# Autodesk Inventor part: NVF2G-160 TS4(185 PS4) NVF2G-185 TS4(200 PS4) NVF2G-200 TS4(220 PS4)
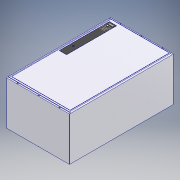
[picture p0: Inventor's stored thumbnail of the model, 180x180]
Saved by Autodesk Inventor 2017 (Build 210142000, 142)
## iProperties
Part Number: NVF2G-160 TS4(185 PS4) NVF2G-185 TS4(200 PS4) NVF2G-200 TS4(220 PS4)
Material: Типовые
Document SubType Name: Modeling
Designer: RSagdiev
Density: 1 g/cm^3
Appearance: По умолчанию
Author: RSagdiev
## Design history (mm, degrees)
sketch "Эскиз1"
  geometry: L1 (0, 0)-(44.679, 0) reference; L2 (0, 0)-(0, 56.035) reference; L3 (0, 0)-(892, 0); L4 (892, 0)-(892, 374.6); L5 (892, 374.6)-(0, 374.6); L6 (0, 374.6)-(0, 0)
  constraints: 12 end point, 3 horizontal, 2 parallel, 2 vertical, 1 perpendicular
  dimensions: "d0" = 892 distance of L5.end L4.end; "d1" = 374.6 distance of L4.end L3.end
extrude "Выдавливание1" new body sketch "Эскиз1" stored distance "d2" = 540; taper "d3" = 0 deg
sketch "Эскиз2"
  geometry: L1 (0, 0)-(0, 892) reference; L2 (540, 0)-(540, 892) reference; L3 (0, 892)-(150, 892); L4 (540, 892)-(540, 880); L5 (540, 0)-(390, 0); L6 (0, 0)-(0, 12); L7 (0, 892)-(540, 892) reference; L8 (0, 892)-(150, 892); L9 (150, 892)-(150, 880); L10 (150, 880)-(0, 880); L11 (0, 880)-(0, 892); L12 (540, 892)-(390, 892); L13 (390, 892)-(390, 880); L14 (390, 880)-(540, 880); L15 (540, 880)-(540, 892); L16 (0, 0)-(540, 0) reference; L17 (0, 0)-(150, 0); L18 (150, 0)-(150, 12); L19 (150, 12)-(0, 12); L20 (0, 12)-(0, 0); L21 (540, 0)-(390, 0); L22 (390, 0)-(390, 12); L23 (390, 12)-(540, 12); L24 (540, 12)-(540, 0); L25 (150, 892)-(390, 892); L26 (0, 880)-(0, 892); L27 (390, 892)-(540, 892); L28 (540, 880)-(540, 12); L29 (390, 0)-(150, 0); L30 (540, 12)-(540, 0); L31 (150, 0)-(0, 0); L32 (0, 12)-(0, 880); L33 (150, 880)-(390, 880); L34 (150, 12)-(390, 12); 1 further point
  constraints: 60 end point, 26 parallel, 13 perpendicular, 7 horizontal
  dimensions: "d4" = 150 distance of L9.end L10.end; "d5" = 12 distance of L3.end L9.end; "d6" = 150 distance of L4.end L13.end; "d7" = 12 distance of L13.end L12.end; "d8" = 150 distance of L6.end L18.end; "d9" = 12 distance of L18.end L17.end; "d10" = 150 distance of L22.end L23.end; "d11" = 12 distance of L5.end L22.end
extrude "Выдавливание2" new body sketch "Эскиз2" distance "d12" = 4; taper "d13" = 0 deg
sketch "Эскиз3"
  geometry: L1 (520, 25)-(520, 876); L2 (20, 876)-(520, 876); L3 (20, 876)-(20, 25); L4 (20, 876)-(520, 876); L5 (20, 25)-(520, 25); L6 (0, 880)-(0, 12) reference; L7 (540, 12)-(540, 880) reference; L8 (0, 892)-(540, 892) reference; L9 (0, 0)-(540, 0) reference; 1 further point
  constraints: 11 end point, 2 perpendicular, 1 horizontal
  dimensions: "d162" = 20 distance between parallel lines of L6 L3 (derived); "d164" = 20 distance between parallel lines of L7 L1; "d203" = 16 distance between parallel lines of L2 L8; "d204" = 25 distance between parallel lines of L9 L5
extrude "Выдавливание3" new body sketch "Эскиз3" distance "d17" = 2; taper "d18" = 0 deg
sketch "Эскиз4"
  geometry: L1 (91, 852)-(32, 852); L2 (30, 850)-(30, 424); L3 (32, 422)-(91, 422); L4 (93, 424)-(93, 850); L5 (0, 892)-(540, 892) reference; L6 (0, 880)-(0, 12) reference; A1 r 2 centre (32, 850) between (32, 852) and (30, 850); A2 r 2 centre (91, 850) between (93, 850) and (91, 852); A3 r 2 centre (91, 424) between (91, 422) and (93, 424); A4 r 2 centre (32, 424) between (30, 424) and (32, 422); 6 further points
  constraints: 8 end point, 8 point on circle, 8 tangent, 6 point on line, 4 centre point, 3 equal radius, 2 parallel, 1 horizontal, 1 perpendicular
  dimensions: "d20" = 63 distance of point (93, 422) point (30, 422); "d21" = 430 distance of point (30, 422) point (30, 852); "d24" = 2 radius of A1; "d165" = 40 distance between parallel lines of L5 L1; "d166" = 30 distance between parallel lines of L6 L2
extrude "Выдавливание4" cut sketch "Эскиз4" distance "d25" = 0.6; taper "d26" = 0 deg
sketch "Эскиз5"
  geometry: L1 (0, 892)-(540, 892) reference; L2 (0, 0)-(0, 892) reference; L3 (540, 892)-(540, 0) reference; L4 (0, 0)-(540, 0) reference; C1 r 5 at (90, 886); C2 r 5 at (270, 886); C3 r 5 at (90, 6); C4 r 5 at (270, 6); C5 r 5 at (450, 886); C6 r 5 at (450, 6); 1 further point
  constraints: 6 centre point
  dimensions: "d27" = 10 diameter of C1; "d28" = 6 distance from line of C1.centre L1; "d30" = 10 diameter of C2; "d31" = 6 distance from line of C2.centre L1; "d33" = 10 diameter of C3; "d34" = 6 distance from line of L4 C3.centre; "d36" = 10 diameter of C4; "d38" = 6 distance from line of C4.centre L4; "d169" = 180 distance of C1.centre C2.centre; "d172" = 180 distance of C4.centre C3.centre (derived); "d205" = 10 diameter of C5; "d206" = 180 distance of C5.centre C2.centre (derived); "d207" = 10 diameter of C6; "d208" = 180 distance of C6.centre C4.centre (derived); "d209" = 540 distance between parallel lines of L3 L2 (derived); "d210" = 90 distance from line of L2 C1.centre (derived); "d211" = 90 distance from line of L2 C3.centre (derived)
extrude "Выдавливание5" cut sketch "Эскиз5" stored distance "d39" = 0.6; taper "d40" = 0 deg
sketch "Эскиз6"
  geometry: L1 (30, 761)-(30, 817); L2 (91, 759)-(32, 759); L3 (93, 850)-(93, 817); L4 (32, 852)-(91, 852); L5 (30, 761)-(30, 850); L6 (30, 817)-(93, 817); L7 (93, 850)-(93, 817); L8 (30, 817)-(30, 850); L9 (93, 817)-(93, 761); L10 (43.5, 828)-(79.5, 828); L11 (81.5, 830)-(81.5, 840); L12 (79.5, 842)-(43.5, 842); L13 (41.5, 840)-(41.5, 830); L14 (41.5, 828)-(81.5, 842); L15 (81.5, 828)-(41.5, 842); L16 (61.5, 805.5)-(61.5, 770.857); L17 (53.25, 805.5)-(53.25, 770.857); L18 (69.75, 770.857)-(69.75, 805.5); L19 (47, 812)-(36, 812); L20 (35, 811)-(35, 800); L21 (36, 799)-(47, 799); L22 (48, 800)-(48, 811); L23 (48, 812)-(35, 799); L24 (35, 812)-(48, 799); L25 (81.5, 830)-(81.5, 765.5); L26 (41.5, 805.5)-(88.409, 805.5); L27 (39.654, 788.179)-(85.729, 788.179); L28 (39.654, 770.857)-(84.963, 770.857); L29 (88, 800)-(88, 811); L30 (76, 799)-(87, 799); L31 (88, 812)-(75, 799); L32 (75, 812)-(88, 799); L33 (75, 811)-(75, 800); L34 (87, 812)-(76, 812); L35 (88, 782.679)-(88, 793.679); L36 (76, 781.679)-(87, 781.679); L37 (88, 794.679)-(75, 781.679); L38 (75, 794.679)-(88, 781.679); L39 (75, 793.679)-(75, 782.679); L40 (87, 794.679)-(76, 794.679); L41 (88, 765.357)-(88, 776.357); L42 (76, 764.357)-(87, 764.357); L43 (88, 777.357)-(75, 764.357); L44 (75, 777.357)-(88, 764.357); L45 (75, 776.357)-(75, 765.357); L46 (87, 777.357)-(76, 777.357); L47 (48, 765.357)-(48, 776.357); L48 (36, 764.357)-(47, 764.357); L49 (48, 777.357)-(35, 764.357); L50 (35, 777.357)-(48, 764.357); L51 (35, 776.357)-(35, 765.357); L52 (47, 777.357)-(36, 777.357); L53 (48, 782.679)-(48, 793.679); L54 (36, 781.679)-(47, 781.679); L55 (48, 794.679)-(35, 781.679); L56 (35, 794.679)-(48, 781.679); L57 (35, 793.679)-(35, 782.679); L58 (47, 794.679)-(36, 794.679); L59 (91, 759)-(32, 759); L60 (0, 892)-(540, 892) reference; L61 (0, 878)-(0, 14); L62 (93, 817)-(93, 761); C1 r 6.5 at (61.5, 805.5); C2 r 6.5 at (61.5, 770.857); C3 r 6.5 at (61.5, 788.179); A1 r 2 centre (43.5, 840) between (43.5, 842) and (41.5, 840); A2 r 2 centre (79.5, 840) between (81.5, 840) and (79.5, 842); A3 r 2 centre (79.5, 830) between (79.5, 828) and (81.5, 830); A4 r 2 centre (43.5, 830) between (41.5, 830) and (43.5, 828); A5 r 8.25 centre (61.5, 805.5) between (69.75, 805.5) and (53.25, 805.5); A6 r 8.25 centre (61.5, 770.857) between (53.25, 770.857) and (69.75, 770.857); A7 r 1 centre (47, 811) between (48, 811) and (47, 812); A8 r 1 centre (47, 800) between (47, 799) and (48, 800); A9 r 1 centre (36, 800) between (35, 800) and (36, 799); A10 r 1 centre (36, 811) between (36, 812) and (35, 811); A11 r 1 centre (87, 800) between (87, 799) and (88, 800); A12 r 1 centre (87, 811) between (88, 811) and (87, 812); A13 r 1 centre (76, 811) between (76, 812) and (75, 811); A14 r 1 centre (76, 800) between (75, 800) and (76, 799); A15 r 1 centre (87, 782.679) between (87, 781.679) and (88, 782.679); A16 r 1 centre (87, 793.679) between (88, 793.679) and (87, 794.679); A17 r 1 centre (76, 793.679) between (76, 794.679) and (75, 793.679); A18 r 1 centre (76, 782.679) between (75, 782.679) and (76, 781.679); A19 r 1 centre (87, 765.357) between (87, 764.357) and (88, 765.357); A20 r 1 centre (87, 776.357) between (88, 776.357) and (87, 777.357); A21 r 1 centre (76, 776.357) between (76, 777.357) and (75, 776.357); A22 r 1 centre (76, 765.357) between (75, 765.357) and (76, 764.357); A23 r 1 centre (47, 765.357) between (47, 764.357) and (48, 765.357); A24 r 1 centre (47, 776.357) between (48, 776.357) and (47, 777.357); A25 r 1 centre (36, 776.357) between (36, 777.357) and (35, 776.357); A26 r 1 centre (36, 765.357) between (35, 765.357) and (36, 764.357); A27 r 1 centre (47, 782.679) between (47, 781.679) and (48, 782.679); A28 r 1 centre (47, 793.679) between (48, 793.679) and (47, 794.679); A29 r 1 centre (36, 793.679) between (36, 794.679) and (35, 793.679); A30 r 1 centre (36, 782.679) between (35, 782.679) and (36, 781.679); A31 r 2 centre (32, 850) between (32, 852) and (30, 850); A32 r 2 centre (91, 850) between (93, 850) and (91, 852); A33 r 2 centre (91, 761) between (91, 759) and (93, 761); A34 r 2 centre (32, 761) between (30, 761) and (32, 759); 15 further points
  constraints: 124 end point, 70 tangent, 68 point on circle, 67 point on line, 37 centre point, 21 equal radius, 15 midpoint, 15 parallel, 11 horizontal, 7 collinear, 7 perpendicular, 3 coincident, 2 vertical
  dimensions: "d43" = 35 distance between parallel lines of L4 L6; "d44" = 40 distance of L15.end L14.end; "d45" = 14 distance of L14.end L15.start; "d46" = 10 distance between parallel lines of L4 L12; "d47" = 2 radius of A1; "d48" = 11.5 distance between parallel lines of L8 L13; "d49" = 16.5 diameter of A6; "d50" = 31.5 distance between parallel lines of L1 L16; "d51" = 11.5 distance from line of L6 L16.start; "d52" = 11.85714 distance from line of L2 L16.end; "d53" = 13 diameter of C1; "d54" = 13 diameter of C2; "d55" = 13 diameter of C3; "d56" = 13 distance of L24.end L23.end; "d57" = 13 distance of L23.end L24.start; "d58" = 1 radius of A7 (derived); "d59" = 11.5 distance from line of L6 L26.start; "d60" = 11.5 distance from line of L5 L26.start; "d61" = 13 distance of L32.end L31.end; "d62" = 13 distance of L31.end L32.start; "d63" = 1 radius of A12 (derived); "d64" = 13 distance of L38.end L37.end; "d65" = 13 distance of L37.end L38.start; "d66" = 1 radius of A16 (derived); "d67" = 13 distance of L44.end L43.end; "d68" = 13 distance of L43.end L44.start; "d69" = 1 radius of A20 (derived); "d70" = 13 distance of L50.end L49.end; "d71" = 13 distance of L49.end L50.start; "d72" = 1 radius of A24 (derived); "d73" = 13 distance of L56.end L55.end; "d74" = 13 distance of L55.end L56.start; "d75" = 1 radius of A28 (derived); "d146" = 40 distance of point (81.5, 805.5) L26.start; "d147" = 4.32143 distance between parallel lines of L40 L30; "d148" = 4.32143 distance between parallel lines of L46 L36; "d149" = 93 distance between parallel lines of L2 L4; "d151" = 2 radius of A31; "d152" = 2 radius of A32; "d153" = 2 radius of A33; "d154" = 2 radius of A34; "d167" = 40 distance between parallel lines of L4 L60 (derived); "d168" = 30 distance between parallel lines of L61 L5 (derived)
extrude "Выдавливание6" new body sketch "Эскиз6" distance "d76" = 0.3; taper "d77" = 0 deg
extrude "Выдавливание7" new body sketch "Эскиз6" distance "d78" = 0.6; taper "d79" = 0 deg
sketch "Эскиз7"
  geometry: L1 (30, 817)-(93, 817) reference; L2 (30, 817)-(93, 817); L3 (93, 817)-(93, 817.1); L4 (93, 817.1)-(30, 817.1); L5 (30, 817.1)-(30, 817); 4 further points; 1 other entity
  constraints: 8 end point, 2 parallel, 1 horizontal, 1 perpendicular, 2 other
  dimensions: "d80" = 0.1 distance of L3.end L2.end
extrude "Выдавливание8" cut sketch "Эскиз7" distance "d81" = 0.3; taper "d82" = 0 deg
sketch "Эскиз8" dims "d91" = 10
  geometry: L1 (30, 817.1)-(93, 817.1) reference; C1 r 1 at (38, 822.1); C2 r 1 at (45.75, 822.1); C3 r 1 at (53.5, 822.1); C4 r 1 at (61.25, 822.1); C5 r 1 at (69, 822.1); C6 r 1 at (76.75, 822.1); C7 r 1 at (84.5, 822.1); 4 further points; 1 other entity
  constraints: 7 centre point, 1 horizontal, 13 other
  dimensions: "d83" = 2 diameter of C1; "d84" = 5 distance from line of C1.centre L1; "d85" = 8 dimension on C1.centre; "d88" = 7.75 distance of C1.centre C2.centre
extrude "Выдавливание9" join sketch "Эскиз8" distance "d93" = 0.3; taper "d94" = 0 deg
sketch "Эскиз9"
  geometry: C1 r 6.5 at (0, 0) reference; C2 r 7.5 at (0, 0); 1 further point
  constraints: 1 centre point, 1 coincident
  dimensions: "d95" = 15 diameter of C2
extrude "Выдавливание10" join sketch "Эскиз9" distance "d96" = 9.4; taper "d97" = -3 deg
sketch "Эскиз10"
  geometry: L1 (0, 7.331)-(0.619, 6.259); L2 (0.619, 6.259)-(-0.619, 6.259); L3 (-0.619, 6.259)-(0, 7.331); 2 further points
  constraints: 6 end point, 7 other
sketch "Эскиз11"
  geometry: L1 (0, 7.917)-(0.884, 6.386); L2 (0.884, 6.386)-(-0.884, 6.386); L3 (-0.884, 6.386)-(0, 7.917); 2 further points
  constraints: 6 end point, 7 other
feature "Лофт1" sketch "Эскиз10", "Эскиз11" dims "d98" = 0, "d99" = 90 deg, "d100" = 0, "d101" = 90 deg
sketch "Эскиз12"
  geometry: L1 (38.299, 807.492)-(44.519, 807.492); L2 (44.519, 807.492)-(44.519, 803.992); L3 (44.519, 803.992)-(38.299, 803.992); L4 (38.299, 803.992)-(38.299, 807.492); L5 (37.349, 790.393)-(46.204, 790.393); L6 (46.204, 790.393)-(46.204, 786.763); L7 (46.204, 786.763)-(37.349, 786.763); L8 (37.349, 786.763)-(37.349, 790.393); L9 (36.992, 773.057)-(46.349, 773.057); L10 (46.349, 773.057)-(46.349, 769.483); L11 (46.349, 769.483)-(36.992, 769.483); L12 (36.992, 769.483)-(36.992, 773.057); L13 (75.821, 773.057)-(87.374, 773.057); L14 (87.374, 773.057)-(87.374, 769.409); L15 (87.374, 769.409)-(75.821, 769.409); L16 (75.821, 769.409)-(75.821, 773.057); L17 (77.603, 790.274)-(85.797, 790.274); L18 (85.797, 790.274)-(85.797, 786.65); L19 (85.797, 786.65)-(77.603, 786.65); L20 (77.603, 786.65)-(77.603, 790.274); L21 (75.703, 807.611)-(88.752, 807.611); L22 (88.752, 807.611)-(88.752, 803.986); L23 (88.752, 803.986)-(75.703, 803.986); L24 (75.703, 803.986)-(75.703, 807.611); 1 further point
  constraints: 12 other
feature "Рельеф1" dims "d4" = 150, "d5" = 12, "d6" = 150, "d7" = 12, "d8" = 150, "d9" = 12, "d10" = 150, "d11" = 12, "d105" = 0.1, "d106" = 0
feature "Рельеф2" dims "d4" = 150, "d5" = 12, "d6" = 150, "d7" = 12, "d8" = 150, "d9" = 12, "d10" = 150, "d11" = 12, "d107" = 0.1, "d108" = 0
feature "Рельеф3" dims "d4" = 150, "d5" = 12, "d6" = 150, "d7" = 12, "d8" = 150, "d9" = 12, "d10" = 150, "d11" = 12, "d109" = 0.1, "d110" = 0
feature "Рельеф4" dims "d4" = 150, "d5" = 12, "d6" = 150, "d7" = 12, "d8" = 150, "d9" = 12, "d10" = 150, "d11" = 12, "d111" = 0.1, "d112" = 0
feature "Рельеф5" dims "d4" = 150, "d5" = 12, "d6" = 150, "d7" = 12, "d8" = 150, "d9" = 12, "d10" = 150, "d11" = 12, "d113" = 0.1, "d114" = 0
feature "Рельеф6" dims "d4" = 150, "d5" = 12, "d6" = 150, "d7" = 12, "d8" = 150, "d9" = 12, "d10" = 150, "d11" = 12, "d115" = 0.1, "d116" = 0
sketch "Эскиз13"
  geometry: L1 (-3.144, -2.347)-(-0.04, 3.728); L2 (-0.04, 3.728)-(3.298, -2.347); L3 (3.298, -2.347)-(2.096, -2.347); L4 (2.096, -2.347)-(-0.04, 1.541); L5 (-0.04, 1.541)-(-2.027, -2.347); L6 (-2.027, -2.347)-(-3.144, -2.347); L7 (-9.387, -8.657)-(8.031, -8.657); L8 (-3.144, -14.967)-(-0.04, -21.041); L9 (-0.04, -21.041)-(3.298, -14.967); L10 (3.298, -14.967)-(2.096, -14.967); L11 (2.096, -14.967)-(-0.04, -18.855); L12 (-0.04, -18.855)-(-2.027, -14.967); L13 (-2.027, -14.967)-(-3.144, -14.967); 1 further point
  constraints: 26 end point, 6 symmetric about line, 2 horizontal, 2 parallel, 2 point on line, 1 collinear
feature "Рельеф7" dims "d4" = 150, "d5" = 12, "d6" = 150, "d7" = 12, "d8" = 150, "d9" = 12, "d10" = 150, "d11" = 12, "d117" = 0.1, "d118" = 0
feature "Рельеф8" dims "d4" = 150, "d5" = 12, "d6" = 150, "d7" = 12, "d8" = 150, "d9" = 12, "d10" = 150, "d11" = 12, "d119" = 0.1, "d120" = 0
sketch "Эскиз14"
  geometry: L1 (57.729, 524.841)-(66.026, 510.47); L2 (66.026, 510.47)-(49.433, 510.47); L3 (49.433, 510.47)-(57.729, 524.841); L4 (64.599, 511.294)-(57.729, 523.192); L5 (57.729, 523.192)-(50.86, 511.294); L6 (50.86, 511.294)-(64.599, 511.294); L7 (56.902, 519.525)-(55.962, 515.715); L8 (55.962, 515.715)-(58.383, 515.885); L9 (58.383, 515.885)-(57.342, 513.569); L10 (57.342, 513.569)-(56.392, 513.996); L11 (56.392, 513.996)-(56.549, 511.765); L12 (56.549, 511.765)-(59.019, 512.815); L13 (59.019, 512.815)-(58.338, 513.121); L14 (58.338, 513.121)-(60.267, 516.757); L15 (60.267, 516.757)-(57.113, 516.574); L16 (57.113, 516.574)-(58.679, 519.525); L17 (58.679, 519.525)-(56.902, 519.525); 2 further points
  constraints: 34 end point, 2 perpendicular, 2 point on line, 1 parallel, 9 other
extrude "Выдавливание11" cut sketch "Эскиз14" distance "d121" = 0.8; taper "d122" = 0 deg
extrude "Выдавливание12" join sketch "Эскиз14" stored distance "d123" = 0.05; taper "d124" = 0 deg
sketch "Эскиз15"
  geometry: L1 (32.937, 826.428)-(56.807, 826.428); L2 (56.807, 826.428)-(56.807, 823.81); L3 (56.807, 823.81)-(32.937, 823.81); L4 (32.937, 823.81)-(32.937, 826.428); L5 (58.162, 825.617)-(88.881, 825.617); L6 (88.881, 825.617)-(88.881, 821.704); L7 (88.881, 821.704)-(58.162, 821.704); L8 (58.162, 821.704)-(58.162, 825.617); L9 (30, 817.1)-(93, 817.1) reference; C1 r 1 at (38, 822.1) reference; 7 further points; 2 other entities
  constraints: 6 other
  dimensions: "d155" = 0.71019 distance edge to line of C1 L3; "d156" = 2.93695 dimension on L4; "d157" = 4.60387 distance between parallel lines of L9 L7; "d158" = 4.11868 dimension on L6
feature "Рельеф9" sketch "Эскиз15" dims "d4" = 150, "d5" = 12, "d6" = 150, "d7" = 12, "d8" = 150, "d9" = 12, "d10" = 150, "d11" = 12, "d125" = 0.1, "d126" = 0
sketch "Эскиз17"
  geometry: L1 (54.534, 359)-(54.534, 352.001); L2 (54.534, 352.001)-(52.465, 352.001); L3 (52.465, 352.001)-(52.465, 359); L4 (52.465, 359)-(54.534, 359); 1 further point
  constraints: 2 other
feature "Рельеф10" sketch "Эскиз17" dims "d4" = 150, "d5" = 12, "d6" = 150, "d7" = 12, "d8" = 150, "d9" = 12, "d10" = 150, "d11" = 12, "d144" = 0.1, "d145" = 0
sketch "Эскиз19" dims "d179" = 10
  geometry: L1 (113.24, 333.958)-(134.375, 351.485); L2 (114.525, 332.409)-(135.66, 349.935); L3 (133.09, 353.034)-(111.955, 335.508); L4 (374.6, 880)-(374.6, 12) reference; L5 (113.24, 323.958)-(134.375, 341.485); L6 (114.525, 322.409)-(135.66, 339.935); L7 (133.09, 343.034)-(111.955, 325.508); L8 (113.24, 313.958)-(134.375, 331.485); L9 (114.525, 312.409)-(135.66, 329.935); L10 (133.09, 333.034)-(111.955, 315.508); L11 (113.24, 303.958)-(134.375, 321.485); L12 (114.525, 302.409)-(135.66, 319.935); L13 (133.09, 323.034)-(111.955, 305.508); L14 (113.24, 293.958)-(134.375, 311.485); L15 (114.525, 292.409)-(135.66, 309.935); L16 (133.09, 313.034)-(111.955, 295.508); L17 (113.24, 283.958)-(134.375, 301.485); L18 (114.525, 282.409)-(135.66, 299.935); L19 (133.09, 303.034)-(111.955, 285.508); L20 (113.24, 273.958)-(134.375, 291.485); L21 (114.525, 272.409)-(135.66, 289.935); L22 (133.09, 293.034)-(111.955, 275.508); L23 (113.24, 263.958)-(134.375, 281.485); L24 (114.525, 262.409)-(135.66, 279.935); L25 (133.09, 283.034)-(111.955, 265.508); L26 (113.24, 253.958)-(134.375, 271.485); L27 (114.525, 252.409)-(135.66, 269.935); L28 (133.09, 273.034)-(111.955, 255.508); L29 (113.24, 243.958)-(134.375, 261.485); L30 (114.525, 242.409)-(135.66, 259.935); L31 (133.09, 263.034)-(111.955, 245.508); A1 r 2.013 centre (113.24, 333.958) between (111.955, 335.508) and (114.525, 332.409); A2 r 2.013 centre (134.375, 351.485) between (135.66, 349.935) and (133.09, 353.034); A3 r 2.013 centre (113.24, 323.958) between (111.955, 325.508) and (114.525, 322.409); A4 r 2.013 centre (134.375, 341.485) between (135.66, 339.935) and (133.09, 343.034); A5 r 2.013 centre (113.24, 313.958) between (111.955, 315.508) and (114.525, 312.409); A6 r 2.013 centre (134.375, 331.485) between (135.66, 329.935) and (133.09, 333.034); A7 r 2.013 centre (113.24, 303.958) between (111.955, 305.508) and (114.525, 302.409); A8 r 2.013 centre (134.375, 321.485) between (135.66, 319.935) and (133.09, 323.034); A9 r 2.013 centre (113.24, 293.958) between (111.955, 295.508) and (114.525, 292.409); A10 r 2.013 centre (134.375, 311.485) between (135.66, 309.935) and (133.09, 313.034); A11 r 2.013 centre (113.24, 283.958) between (111.955, 285.508) and (114.525, 282.409); A12 r 2.013 centre (134.375, 301.485) between (135.66, 299.935) and (133.09, 303.034); A13 r 2.013 centre (113.24, 273.958) between (111.955, 275.508) and (114.525, 272.409); A14 r 2.013 centre (134.375, 291.485) between (135.66, 289.935) and (133.09, 293.034); A15 r 2.013 centre (113.24, 263.958) between (111.955, 265.508) and (114.525, 262.409); A16 r 2.013 centre (134.375, 281.485) between (135.66, 279.935) and (133.09, 283.034); A17 r 2.013 centre (113.24, 253.958) between (111.955, 255.508) and (114.525, 252.409); A18 r 2.013 centre (134.375, 271.485) between (135.66, 269.935) and (133.09, 273.034); A19 r 2.013 centre (113.24, 243.958) between (111.955, 245.508) and (114.525, 242.409); A20 r 2.013 centre (134.375, 261.485) between (135.66, 259.935) and (133.09, 263.034); 13 further points
  constraints: 80 end point, 40 point on circle, 20 centre point, 4 tangent, 1 midpoint, 1 parallel, 1 vertical, 108 other
  dimensions: "d176" = 10 distance of L2.start L6.start
extrude "Выдавливание14" cut sketch "Эскиз19" distance "d181" = 10; taper "d182" = 0 deg
sketch "Эскиз20" dims "d191" = 10, "d198" = 10
  geometry: L1 (374.6, 2)-(0, 2) reference; L2 (0, 892)-(0, 0) reference; C1 r 2 at (15, 132); C2 r 2 at (20, 132); C3 r 2 at (25, 132); C4 r 2 at (30, 132); C5 r 2 at (35, 132); C6 r 2 at (40, 132); C7 r 2 at (45, 132); C8 r 2 at (50, 132); C9 r 2 at (55, 132); C10 r 2 at (60, 132); C11 r 2 at (65, 132); C12 r 2 at (70, 132); C13 r 2 at (70, 127); C14 r 2 at (65, 127); C15 r 2 at (60, 127); C16 r 2 at (55, 127); C17 r 2 at (15, 127); C18 r 2 at (20, 127); C19 r 2 at (25, 127); C20 r 2 at (30, 127); C21 r 2 at (35, 127); C22 r 2 at (40, 127); C23 r 2 at (45, 127); C24 r 2 at (50, 127); C25 r 2 at (70, 122); C26 r 2 at (65, 122); C27 r 2 at (60, 122); C28 r 2 at (55, 122); C29 r 2 at (15, 122); C30 r 2 at (20, 122); C31 r 2 at (25, 122); C32 r 2 at (30, 122); C33 r 2 at (35, 122); C34 r 2 at (40, 122); C35 r 2 at (45, 122); C36 r 2 at (50, 122); C37 r 2 at (70, 117); C38 r 2 at (65, 117); C39 r 2 at (60, 117); C40 r 2 at (55, 117); C41 r 2 at (15, 117); C42 r 2 at (20, 117); C43 r 2 at (25, 117); C44 r 2 at (30, 117); C45 r 2 at (35, 117); C46 r 2 at (40, 117); C47 r 2 at (45, 117); C48 r 2 at (50, 117); C49 r 2 at (70, 112); C50 r 2 at (65, 112); C51 r 2 at (60, 112); C52 r 2 at (55, 112); C53 r 2 at (15, 112); C54 r 2 at (20, 112); C55 r 2 at (25, 112); C56 r 2 at (30, 112); C57 r 2 at (35, 112); C58 r 2 at (40, 112); C59 r 2 at (45, 112); C60 r 2 at (50, 112); C61 r 2 at (70, 107); C62 r 2 at (65, 107); C63 r 2 at (60, 107); C64 r 2 at (55, 107)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; 1 further point
  constraints: 240 centre point, 1 horizontal, 1 vertical, 478 other
  dimensions: "d183" = 4 diameter of C1; "d184" = 15 distance from line of L2 C1.centre; "d185" = 130 distance from line of L1 C1.centre; "d188" = 5 distance of C1.centre C2.centre; "d195" = 5 distance of C12.centre C13.centre
extrude "Выдавливание15" cut sketch "Эскиз20" distance "d200" = 15; taper "d201" = 0 deg
fillet "Сопряжение3" dims "d212" = 20
fillet "Сопряжение4" dims "d213" = 2
node "Твердое тело1"
pattern_circular "Круговой массив1" dims angle "d103" = 360 deg
node "Твердое тело2"
node "Твердое тело3"
node "Твердое тело4"
node "Твердое тело5"
